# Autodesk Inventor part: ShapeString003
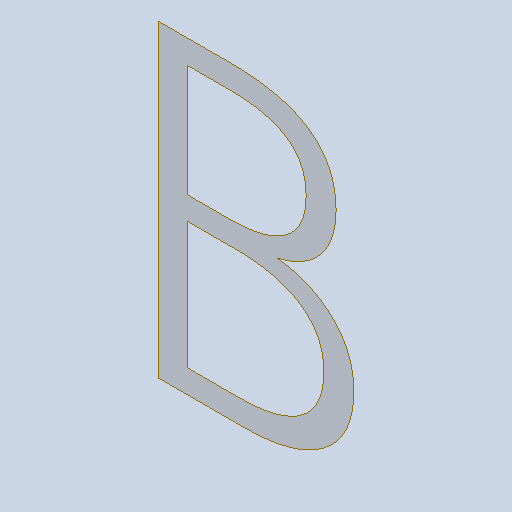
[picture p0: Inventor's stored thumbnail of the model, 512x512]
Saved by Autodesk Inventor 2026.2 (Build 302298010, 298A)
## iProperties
Created: 2026-10
Part Number: ShapeString003
Material: Générique
Document SubType Name: Modeling
Designer: mel
Density: 1 g/cm^3
Appearance: Par défaut
Author: mel
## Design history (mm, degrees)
feature "Composite1"
body "Srf1"
